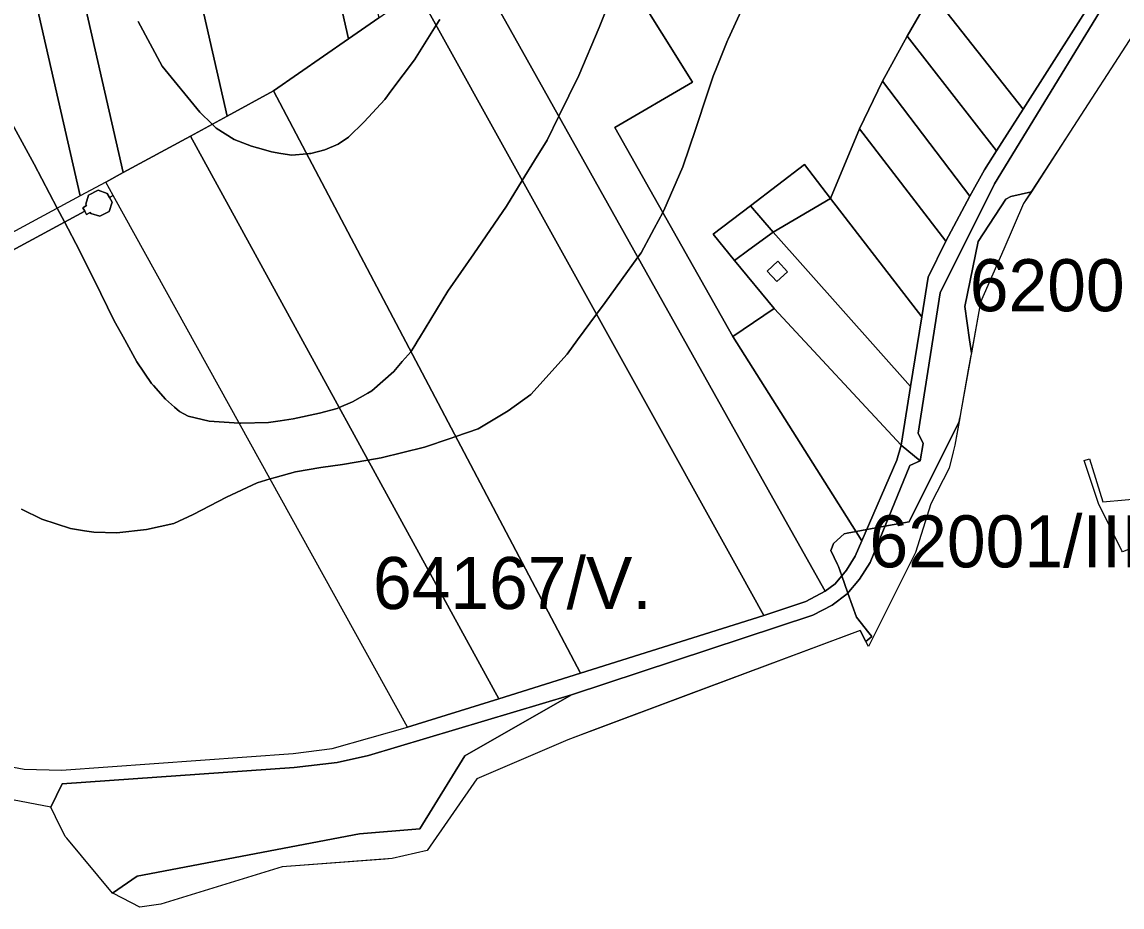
# Model space of a CAD drawing. Extents: x -521939 to -516426, y -1197857 to -1189551.
# Drawn here: x -519681.9 to -519365, y -1194163.4 to -1193908.4 of the extents above; entities that cross this region are included whole.
import ezdxf

# ---------------------------------------------------------------- set-up
doc = ezdxf.new("R2010")
doc.units = 0
for name, color, linetype in [('95560013', 7, 'Continuous'), ('95610013', 7, 'Continuous'), ('95630013', 7, 'Continuous'), ('95640013', 7, 'Continuous'), ('95660013', 7, 'Continuous')]:
    doc.layers.add(name, color=color, linetype=linetype)

msp = doc.modelspace()

# ---------------------------------------------------------------- linework, layer by layer
at = {"layer": '95560013'}
for points in [[(-519701.52, -1193414.64), (-519691.78, -1193412.9), (-519651.6, -1193589.16), (-519612.48, -1193760.77), (-519579.1, -1193907.2), (-519587.75, -1193913.3)], [(-519739.99, -1193421.5), (-519725.47, -1193418.95), (-519701.52, -1193414.64), (-519587.75, -1193913.3), (-519609.4, -1193928.24), (-519622.78, -1193935.57)], [(-519652.7, -1193951.75), (-519692.33, -1193778.37), (-519736.87, -1193583.51), (-519772.58, -1193427.28), (-519739.99, -1193421.5), (-519622.78, -1193935.57), (-519633.36, -1193941.29)], [(-519652.7, -1193951.75), (-519657.74, -1193954.5), (-519665.13, -1193958.51), (-519682.62, -1193881.84), (-519704.7, -1193785.08), (-519745.25, -1193607.38), (-519785.8, -1193429.68), (-519772.58, -1193427.28), (-519736.87, -1193583.51), (-519692.33, -1193778.37)], [(-519665.13, -1193958.51), (-519687.29, -1193970.52), (-519709.36, -1193889.56), (-519682.62, -1193881.84)], [(-519374.32, -1194034.25), (-519370.51, -1194046.68), (-519319.06, -1194042.03), (-519330.1, -1194047.22), (-519364.84, -1194061.02), (-519364.98, -1194060.74), (-519371.75, -1194047.1), (-519375.87, -1194034.77)]]:
    msp.add_lwpolyline(points, close=True, dxfattribs=at)
at = {"layer": '95610013'}
for points in [[(-519524.03, -1193869.16), (-519488.68, -1193925.71), (-519511.04, -1193938.78), (-519477.05, -1193998.98), (-519450.62, -1194041.02), (-519444.35, -1194050.85), (-519439.91, -1194057.85), (-519441.81, -1194062.27), (-519444.29, -1194066.37), (-519447.56, -1194070.22), (-519450.52, -1194072.35), (-519465.54, -1194045.55), (-519553.25, -1193889.05), (-519536.51, -1193877.89)], [(-519553.25, -1193889.05), (-519465.54, -1194045.55), (-519450.52, -1194072.35), (-519456, -1194075.37), (-519468.13, -1194079.41), (-519475.09, -1194066.87), (-519568.04, -1193899.4)], [(-519468.13, -1194079.41), (-519520.93, -1194095.96), (-519609.4, -1193928.24), (-519587.75, -1193913.3), (-519579.1, -1193907.2), (-519568.04, -1193899.4), (-519475.09, -1194066.87)], [(-519426.85, -1193912.47), (-519419.72, -1193900.08), (-519393.46, -1193933.48), (-519401.16, -1193945.56)], [(-519401.16, -1193945.56), (-519404.57, -1193950.95), (-519408.84, -1193958.58), (-519433.98, -1193925.44), (-519426.85, -1193912.47)], [(-519440.59, -1193939.19), (-519433.98, -1193925.44), (-519408.84, -1193958.58), (-519415.68, -1193971.51)], [(-519544.51, -1194103.35), (-519633.36, -1193941.29), (-519622.78, -1193935.57), (-519609.4, -1193928.24), (-519520.93, -1194095.96)], [(-519448.9, -1193959.21), (-519440.59, -1193939.19), (-519415.68, -1193971.51), (-519420.77, -1193981.9), (-519422.59, -1193993.31)], [(-519544.51, -1194103.35), (-519570.8, -1194111.59), (-519655.57, -1193958.42), (-519657.74, -1193954.5), (-519652.7, -1193951.75), (-519633.36, -1193941.29)], [(-519448.9, -1193959.21), (-519465.49, -1193968.92), (-519472.03, -1193961.35), (-519456.43, -1193949.45)], [(-519472.03, -1193961.35), (-519465.49, -1193968.92), (-519472.45, -1193974.05), (-519476.58, -1193977.08), (-519482.78, -1193969.56)], [(-519465.49, -1193968.92), (-519448.9, -1193959.21), (-519422.59, -1193993.31), (-519425.91, -1194013.45)], [(-519425.91, -1194013.45), (-519428.22, -1194027.94), (-519428.59, -1194030.27), (-519465.18, -1193990.9), (-519476.58, -1193977.08), (-519472.45, -1193974.05), (-519465.49, -1193968.92)], [(-519464.41, -1193983.21), (-519461.33, -1193980.36), (-519464.11, -1193977.34), (-519467.19, -1193980.19)], [(-519477.05, -1193998.98), (-519465.18, -1193990.9), (-519428.59, -1194030.27), (-519429.83, -1194034.63), (-519439.91, -1194057.85), (-519444.35, -1194050.85), (-519450.62, -1194041.02)], [(-519673.57, -1194134.61), (-519670.24, -1194127.92), (-519603.49, -1194123.15), (-519591.02, -1194121.72), (-519582.05, -1194119.69), (-519523.58, -1194102.28), (-519554.3, -1194119.84), (-519567.25, -1194140.88), (-519584.65, -1194142.29), (-519648.63, -1194154.46), (-519655.75, -1194159.37), (-519668.94, -1194143.55), (-519669.38, -1194143.02), (-519672.17, -1194137.42)]]:
    msp.add_lwpolyline(points, close=True, dxfattribs=at)
for points in [[(-519656.64, -1193959), (-519655.91, -1193960.31), (-519656.75, -1193962.97), (-519659.4, -1193964.35), (-519662.02, -1193963.62), (-519662.24, -1193963.25), (-519663.26, -1193963.82), (-519663.79, -1193962.87)], [(-519655.57, -1193958.42), (-519656.64, -1193959)], [(-519570.8, -1194111.59), (-519655.57, -1193958.42)], [(-519663.79, -1193962.87), (-519734.84, -1194001.31), (-519738.79, -1194005.72), (-519756.49, -1194015.3), (-519786.98, -1194028.03)], [(-519592.47, -1194117.69), (-519570.8, -1194111.59)], [(-519700.28, -1194120.14), (-519681.19, -1194123.7)], [(-519681.19, -1194123.7), (-519670.52, -1194123.93), (-519603.77, -1194119.16)], [(-519603.77, -1194119.16), (-519592.47, -1194117.69)]]:
    msp.add_lwpolyline(points, dxfattribs=at)
at = {"layer": '95630013'}
msp.add_lwpolyline([(-519361.83, -1193912.1), (-519380, -1193940.17), (-519393.3, -1193960.72), (-519399.04, -1193973.83), (-519405.75, -1193989.16), (-519413.11, -1194030.31), (-519413.61, -1194032.27), (-519414.79, -1194036.92), (-519420.05, -1194047.18), (-519424.43, -1194061.23), (-519438.01, -1194088.36), (-519440.38, -1194083.75), (-519524.59, -1194115.17), (-519550.87, -1194126.48), (-519565.1, -1194147.14), (-519575.26, -1194149.43), (-519606.91, -1194151.78), (-519641.85, -1194162.57), (-519647.94, -1194163.37), (-519655.45, -1194159.52), (-519655.75, -1194159.37), (-519648.63, -1194154.46), (-519584.65, -1194142.29), (-519567.25, -1194140.88), (-519554.3, -1194119.84), (-519523.58, -1194102.28), (-519453.99, -1194079.26), (-519448.49, -1194076.43), (-519444.16, -1194073.19), (-519440.57, -1194068.9), (-519437.56, -1194064.1), (-519426.12, -1194036.14), (-519423.14, -1194034.81), (-519422.25, -1194029.85), (-519423.71, -1194026.84), (-519417.38, -1193986.45), (-519401.67, -1193955.07), (-519392.44, -1193939.94), (-519369.32, -1193902.04)], dxfattribs=at)
at = {"layer": '95640013'}
for points in [[(-519369.96, -1193896.6), (-519393.46, -1193933.48), (-519419.72, -1193900.08), (-519426.85, -1193912.47), (-519433.98, -1193925.44), (-519440.59, -1193939.19), (-519448.9, -1193959.21), (-519456.43, -1193949.45), (-519472.03, -1193961.35), (-519482.78, -1193969.56), (-519476.58, -1193977.08), (-519465.18, -1193990.9), (-519477.05, -1193998.98), (-519511.04, -1193938.78), (-519488.68, -1193925.71), (-519524.03, -1193869.16)], [(-519657.74, -1193954.5), (-519665.13, -1193958.51)], [(-519655.57, -1193958.42), (-519657.74, -1193954.5)], [(-519665.13, -1193958.51), (-519687.29, -1193970.52)], [(-519664.31, -1193961.92), (-519663.23, -1193961.31), (-519663.44, -1193960.89), (-519662.65, -1193958.29), (-519659.93, -1193956.89), (-519657.33, -1193957.77), (-519656.64, -1193959)], [(-519656.64, -1193959), (-519657.33, -1193957.77), (-519659.93, -1193956.89), (-519662.65, -1193958.29), (-519663.44, -1193960.89), (-519663.23, -1193961.31), (-519664.31, -1193961.92)], [(-519663.79, -1193962.87), (-519663.26, -1193963.82), (-519662.24, -1193963.25), (-519662.02, -1193963.62), (-519659.4, -1193964.35), (-519656.75, -1193962.97), (-519655.91, -1193960.31), (-519656.64, -1193959)], [(-519656.64, -1193959), (-519655.57, -1193958.42)], [(-519663.79, -1193962.87), (-519664.31, -1193961.92)], [(-519664.31, -1193961.92), (-519663.79, -1193962.87)], [(-519786.98, -1194028.03), (-519756.49, -1194015.3), (-519738.79, -1194005.72), (-519734.84, -1194001.31), (-519663.79, -1193962.87)], [(-519700.28, -1194120.14), (-519681.19, -1194123.7), (-519670.52, -1194123.93), (-519603.77, -1194119.16), (-519592.47, -1194117.69), (-519570.8, -1194111.59), (-519544.51, -1194103.35), (-519520.93, -1194095.96), (-519468.13, -1194079.41), (-519456, -1194075.37), (-519450.52, -1194072.35), (-519447.56, -1194070.22), (-519444.29, -1194066.37), (-519441.81, -1194062.27), (-519439.91, -1194057.85), (-519429.83, -1194034.63), (-519428.59, -1194030.27), (-519423.14, -1194034.81), (-519426.12, -1194036.14), (-519437.56, -1194064.1), (-519440.57, -1194068.9), (-519444.16, -1194073.19), (-519448.49, -1194076.43), (-519453.99, -1194079.26), (-519523.58, -1194102.28), (-519582.05, -1194119.69), (-519591.02, -1194121.72), (-519603.49, -1194123.15), (-519670.24, -1194127.92), (-519673.57, -1194134.61), (-519691.18, -1194131.21)]]:
    msp.add_lwpolyline(points, dxfattribs=at)
for points in [[(-519393.46, -1193933.48), (-519369.96, -1193896.6), (-519369.32, -1193902.04), (-519392.44, -1193939.94), (-519401.67, -1193955.07), (-519417.38, -1193986.45), (-519423.71, -1194026.84), (-519422.25, -1194029.85), (-519423.14, -1194034.81), (-519428.59, -1194030.27), (-519428.22, -1194027.94), (-519425.91, -1194013.45), (-519422.59, -1193993.31), (-519420.77, -1193981.9), (-519415.68, -1193971.51), (-519408.84, -1193958.58), (-519404.57, -1193950.95), (-519401.16, -1193945.56)], [(-519464.11, -1193977.34), (-519461.33, -1193980.36), (-519464.41, -1193983.21), (-519467.19, -1193980.19)]]:
    msp.add_lwpolyline(points, close=True, dxfattribs=at)
at = {"layer": '95660013'}
for points in [[(-519682.02, -1194048.78), (-519676.11, -1194051.68), (-519667.88, -1194054.35), (-519663.82, -1194054.98), (-519661.15, -1194055.39), (-519654.55, -1194055.62), (-519645.97, -1194054.58), (-519638.09, -1194052.84), (-519632.52, -1194050.29), (-519622.9, -1194045.31), (-519614.09, -1194041.13), (-519610.39, -1194040.06), (-519608.88, -1194039.63), (-519603.08, -1194038), (-519595.72, -1194036.73), (-519589.52, -1194035.92), (-519582.19, -1194034.62), (-519578.39, -1194033.95), (-519565.87, -1194030.93), (-519558.46, -1194028.38), (-519556.87, -1194027.83), (-519550.46, -1194025.6), (-519541.77, -1194020.39), (-519535.27, -1194015.75), (-519524.84, -1194004.1), (-519521.8, -1194000), (-519516.31, -1193992.6), (-519513.83, -1193989.26), (-519504.43, -1193976.17), (-519503.51, -1193974.89), (-519500.5, -1193969.34), (-519499.71, -1193967.88), (-519497.21, -1193963.27), (-519496.91, -1193962.72), (-519491.46, -1193950.09), (-519487.75, -1193939.07), (-519484.5, -1193929.24), (-519482.77, -1193924.01), (-519481.73, -1193921.44), (-519478.59, -1193913.69), (-519478.44, -1193913.36), (-519467.12, -1193888.54)], [(-519467.12, -1193888.54), (-519478.44, -1193913.36), (-519478.59, -1193913.69), (-519481.73, -1193921.44), (-519482.77, -1193924.01), (-519484.5, -1193929.24), (-519487.75, -1193939.07), (-519491.46, -1193950.09), (-519496.91, -1193962.72), (-519497.21, -1193963.27), (-519499.71, -1193967.88), (-519500.5, -1193969.34), (-519503.51, -1193974.89), (-519504.43, -1193976.17), (-519513.83, -1193989.26), (-519516.31, -1193992.6), (-519521.8, -1194000), (-519524.84, -1194004.1), (-519535.27, -1194015.75), (-519541.77, -1194020.39), (-519550.46, -1194025.6), (-519556.87, -1194027.83), (-519558.46, -1194028.38), (-519565.87, -1194030.93), (-519578.39, -1194033.95), (-519582.19, -1194034.62), (-519589.52, -1194035.92), (-519595.72, -1194036.73), (-519603.08, -1194038), (-519608.88, -1194039.63), (-519610.39, -1194040.06), (-519614.09, -1194041.13), (-519622.9, -1194045.31), (-519632.52, -1194050.29), (-519638.09, -1194052.84), (-519645.97, -1194054.58), (-519654.55, -1194055.62), (-519661.15, -1194055.39), (-519663.82, -1194054.98), (-519667.88, -1194054.35), (-519676.11, -1194051.68), (-519682.02, -1194048.78)], [(-519702.81, -1193904.62), (-519678.35, -1193949.36), (-519671.68, -1193962.06), (-519669.6, -1193966.01), (-519665.25, -1193974.28), (-519659.17, -1193986.58), (-519655.29, -1193994.45), (-519653.18, -1193998.28), (-519652.23, -1194000), (-519648.79, -1194006.27), (-519644.51, -1194012.53), (-519643.96, -1194013.16), (-519640.56, -1194017.05), (-519637.97, -1194019.35), (-519636.51, -1194020.65), (-519633.96, -1194021.92), (-519627.93, -1194023.43), (-519619.29, -1194023.98), (-519618.77, -1194024.01), (-519610.89, -1194023.78), (-519607.45, -1194023.28), (-519603.71, -1194022.73), (-519596.17, -1194021.11), (-519591.07, -1194019.72), (-519590.49, -1194019.48), (-519586.67, -1194017.86), (-519582.25, -1194015.29), (-519581.1, -1194014.62), (-519574.73, -1194009.06), (-519572.3, -1194006.24), (-519571.45, -1194005.25), (-519569.79, -1194003.33), (-519569.63, -1194003.14), (-519568.67, -1194001.56), (-519567.71, -1194000), (-519567.37, -1193999.43), (-519559.2, -1193985.99), (-519551.73, -1193975.15), (-519542.27, -1193961.42), (-519537.72, -1193954.03), (-519534.17, -1193948.26), (-519530.57, -1193942.41), (-519527.19, -1193935.56), (-519521.41, -1193923.86), (-519515.61, -1193909.95), (-519508.91, -1193893.35)], [(-519508.91, -1193893.35), (-519515.61, -1193909.95), (-519521.41, -1193923.86), (-519527.19, -1193935.56), (-519530.57, -1193942.41), (-519534.17, -1193948.26), (-519537.72, -1193954.03), (-519542.27, -1193961.42), (-519551.73, -1193975.15), (-519559.2, -1193985.99), (-519567.37, -1193999.43), (-519567.71, -1194000), (-519568.67, -1194001.56), (-519569.63, -1194003.14), (-519569.79, -1194003.33), (-519571.45, -1194005.25), (-519572.3, -1194006.24), (-519574.73, -1194009.06), (-519581.1, -1194014.62), (-519582.25, -1194015.29), (-519586.67, -1194017.86), (-519590.49, -1194019.48), (-519591.07, -1194019.72), (-519596.17, -1194021.11), (-519603.71, -1194022.73), (-519607.45, -1194023.28), (-519610.89, -1194023.78), (-519618.77, -1194024.01), (-519619.29, -1194023.98), (-519627.93, -1194023.43), (-519633.96, -1194021.92), (-519636.51, -1194020.65), (-519637.97, -1194019.35), (-519640.56, -1194017.05), (-519643.96, -1194013.16), (-519644.51, -1194012.53), (-519648.79, -1194006.27), (-519652.23, -1194000), (-519653.18, -1193998.28), (-519655.29, -1193994.45), (-519659.17, -1193986.58), (-519665.25, -1193974.28), (-519669.6, -1193966.01), (-519671.68, -1193962.06), (-519678.35, -1193949.36), (-519702.81, -1193904.62)], [(-519561.46, -1193907.69), (-519562.51, -1193909.36), (-519568.76, -1193919.28), (-519575.27, -1193927.99), (-519577.34, -1193930.76), (-519583.25, -1193937.13), (-519587.77, -1193941.54), (-519590.78, -1193943.62), (-519594.61, -1193945.25), (-519598.66, -1193946.29), (-519598.99, -1193946.32), (-519599.83, -1193946.39), (-519604.11, -1193946.75), (-519607.31, -1193946.25), (-519610.02, -1193945.83), (-519612.33, -1193945.17), (-519615.7, -1193944.2), (-519620.69, -1193942.23), (-519625.9, -1193938.99), (-519627.04, -1193937.87), (-519630.65, -1193934.35), (-519641.43, -1193921.14), (-519648.39, -1193908.27)], [(-519648.39, -1193908.27), (-519641.43, -1193921.14), (-519630.65, -1193934.35), (-519627.04, -1193937.87), (-519625.9, -1193938.99), (-519620.69, -1193942.23), (-519615.7, -1193944.2), (-519612.33, -1193945.17), (-519610.02, -1193945.83), (-519607.31, -1193946.25), (-519604.11, -1193946.75), (-519599.83, -1193946.39), (-519598.99, -1193946.32), (-519598.66, -1193946.29), (-519594.61, -1193945.25), (-519590.78, -1193943.62), (-519587.77, -1193941.54), (-519583.25, -1193937.13), (-519577.34, -1193930.76), (-519575.27, -1193927.99), (-519568.76, -1193919.28), (-519562.51, -1193909.36), (-519561.46, -1193907.69)], [(-519361.83, -1193912.1), (-519380, -1193940.17), (-519391.08, -1193957.29), (-519396.95, -1193958.71), (-519398.4, -1193959.46), (-519406.43, -1193971.67), (-519410.23, -1193990.38), (-519408.89, -1194000), (-519408.36, -1194003.76), (-519408.58, -1194004.96), (-519409.24, -1194008.65), (-519411.69, -1194022.35), (-519411.71, -1194022.48), (-519411.9, -1194023.53), (-519426.25, -1194052.42), (-519433.31, -1194053.7), (-519438.52, -1194054.65), (-519439.98, -1194054.92), (-519441.58, -1194055.21), (-519444.12, -1194055.68), (-519445.02, -1194055.84), (-519448.04, -1194058.61), (-519448.45, -1194059.67), (-519448.85, -1194060.68), (-519446.9, -1194064.73), (-519446.65, -1194065.26), (-519445.67, -1194068), (-519444.9, -1194070.17), (-519443.93, -1194072.91), (-519441.46, -1194079.83), (-519437.85, -1194084.38), (-519437, -1194085.46), (-519438.75, -1194086.92), (-519440.38, -1194083.75), (-519489.81, -1194102.19), (-519517.02, -1194112.34), (-519524.59, -1194115.17), (-519550.87, -1194126.48), (-519565.1, -1194147.14), (-519575.26, -1194149.43)], [(-519405.75, -1193989.16), (-519408.36, -1194003.76), (-519408.89, -1194000), (-519410.23, -1193990.38), (-519406.43, -1193971.67), (-519398.4, -1193959.46), (-519396.95, -1193958.71), (-519391.08, -1193957.29), (-519393.3, -1193960.72), (-519399.04, -1193973.83), (-519405.75, -1193989.16)], [(-519364.84, -1194061.02), (-519364.98, -1194060.74), (-519371.75, -1194047.1), (-519375.87, -1194034.77), (-519374.32, -1194034.25), (-519370.51, -1194046.68), (-519319.06, -1194042.03)], [(-519575.26, -1194149.43), (-519577.21, -1194149.57), (-519606.91, -1194151.78), (-519641.85, -1194162.57), (-519647.94, -1194163.37), (-519655.45, -1194159.52), (-519655.75, -1194159.37), (-519668.94, -1194143.55), (-519669.38, -1194143.02), (-519672.17, -1194137.42), (-519673.57, -1194134.61), (-519691.18, -1194131.21)]]:
    msp.add_lwpolyline(points, dxfattribs=at)
msp.add_lwpolyline([(-519440.38, -1194083.75), (-519438.75, -1194086.92), (-519437, -1194085.46), (-519437.85, -1194084.38), (-519441.46, -1194079.83), (-519443.93, -1194072.91), (-519444.9, -1194070.17), (-519445.67, -1194068), (-519446.65, -1194065.26), (-519446.9, -1194064.73), (-519448.85, -1194060.68), (-519448.45, -1194059.67), (-519448.04, -1194058.61), (-519445.02, -1194055.84), (-519444.12, -1194055.68), (-519441.58, -1194055.21), (-519439.98, -1194054.92), (-519438.52, -1194054.65), (-519433.31, -1194053.7), (-519426.25, -1194052.42), (-519411.9, -1194023.53), (-519411.71, -1194022.48), (-519413.11, -1194030.31), (-519413.61, -1194032.27), (-519414.79, -1194036.92), (-519420.05, -1194047.18), (-519424.43, -1194061.23), (-519438.01, -1194088.36)], close=True, dxfattribs=at)

# ---------------------------------------------------------------- texts
for s, rotation, p in [('62001/III.', 0, (-519408.82, -1193991.74)), ('62001/III.', 360, (-519437.72, -1194065.53)), ('64167/V.', 360, (-519580.75, -1194077.53))]:
    msp.add_text(s, height=15, rotation=rotation, dxfattribs=at).set_placement(p)

doc.saveas('drawing.dxf')
